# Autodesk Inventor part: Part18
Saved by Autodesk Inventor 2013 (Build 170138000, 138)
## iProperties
Created: 2012-07
Part Number: Part18
Material: Generic
Document SubType Name: Modeling
Designer: Paul
Density: 1 g/cm^3
Author: Paul
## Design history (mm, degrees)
node "User Library-Arduino Mega.SAT1"
body "Solid1"
node "Base1"
